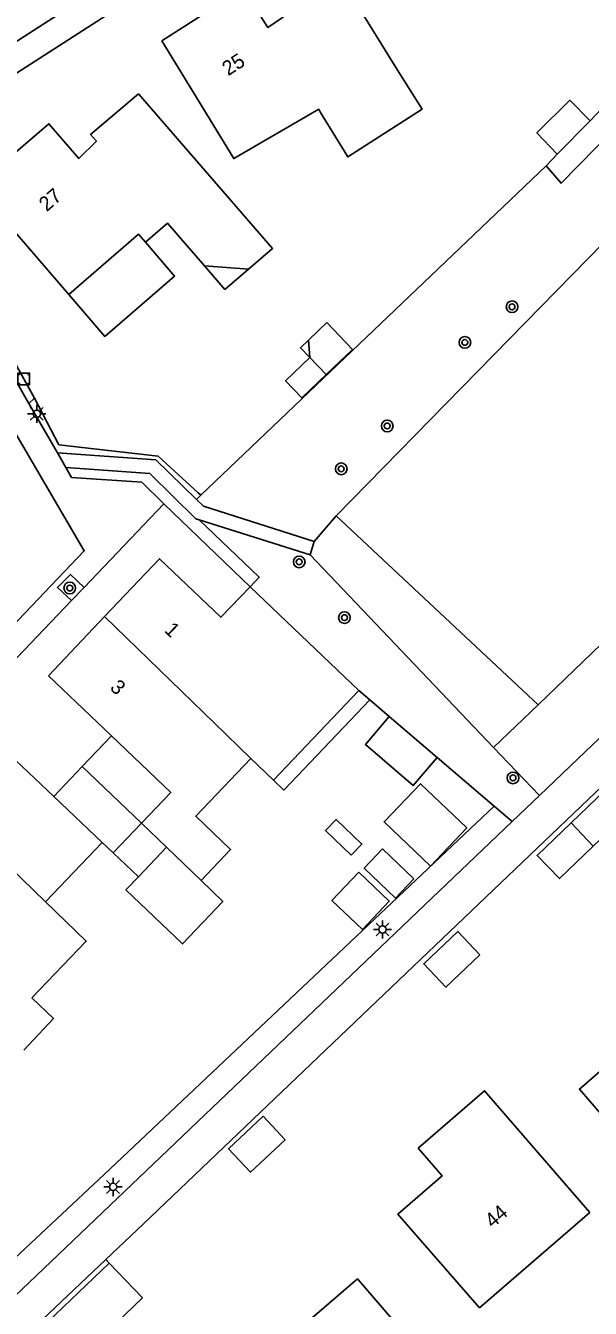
# Model space of a CAD drawing. Extents: x 136000 to 141014, y 402000 to 403500.
# Drawn here: x 137574.1 to 137612.8, y 402325.2 to 402412.9 of the extents above; entities that cross this region are included whole.
import ezdxf

# ---------------------------------------------------------------- set-up
doc = ezdxf.new("R2010")
doc.units = 0
for name, color, linetype in [('gg-afsc-erfafscheiding', 7, 'Continuous'), ('gg-afsc-haag', 7, 'Continuous'), ('gg-anno-huisnummerreeks BGT', 7, 'Continuous'), ('gg-bbg-bijgebouw', 7, 'Continuous'), ('gg-bbg-gedigitaliseerde bebouwing', 7, 'Continuous'), ('gg-bbg-gedigitaliseerde bijgebouw', 7, 'Continuous'), ('gg-bbg-hoofdgebouw', 7, 'Continuous'), ('gg-bbg-luifel en loopbrug', 7, 'Continuous'), ('gg-bbg-tussenscheiding', 7, 'Continuous'), ('gg-knt-verharding', 7, 'Continuous'), ('gg-knt-verharding nz', 7, 'Continuous'), ('gt-grn-groengrens', 7, 'Continuous'), ('gt-grn-vlakafsluiter', 7, 'Continuous'), ('gt-symb-bak', 7, 'Continuous'), ('gt-symb-boom', 7, 'Continuous'), ('gt-symb-lichtmast', 7, 'Continuous')]:
    doc.layers.add(name, color=color, linetype=linetype)

# ---------------------------------------------------------------- blocks, each defined once
blk = doc.blocks.new('gt0-BOOM')
at = {"layer": 'gt-symb-boom'}
for radius in [0.4, 0.2]:
    blk.add_circle((0, 0), radius, dxfattribs=at)
blk = doc.blocks.new('gt0-BAK')
at = {"layer": 'gt-symb-bak'}
for points in [[(-0.3, 0.4), (-0.3, 0.3), (-0.4, 0.3)], [(0.4, 0.3), (0.3, 0.3), (0.3, 0.4)], [(-0.4, -0.3), (-0.3, -0.3), (-0.3, -0.4)], [(0.3, -0.4), (0.3, -0.3), (0.4, -0.3)]]:
    blk.add_lwpolyline(points, dxfattribs=at)
blk.add_lwpolyline([(0.4, -0.4), (-0.4, -0.4), (-0.4, 0.4), (0.4, 0.4)], close=True, dxfattribs=at)
blk = doc.blocks.new('gt0-LMAST')
at = {"layer": 'gt-symb-lichtmast'}
for p, q in [((-0.182, 0.173), (-0.447, 0.438)), ((-0.005, 0.246), (-0.005, 0.621)), ((0.172, 0.173), (0.437, 0.438)), ((-0.255, -0.004), (-0.63, -0.004)), ((-0.182, -0.181), (-0.447, -0.446)), ((-0.005, -0.254), (-0.005, -0.629)), ((0.437, -0.446), (0.172, -0.181)), ((0.245, -0.004), (0.62, -0.004))]:
    blk.add_line(p, q, dxfattribs=at)
blk.add_circle((-0.005, -0.004), 0.25, dxfattribs=at)

msp = doc.modelspace()

# ---------------------------------------------------------------- linework, layer by layer
at = {"layer": 'gg-afsc-erfafscheiding'}
for p, q in [((137612.743, 402406.376), (137614.277, 402407.986)), ((137609.732, 402403.306), (137610.487, 402404.097)), ((137583.58, 402380.19), (137587.723, 402376.195)), ((137587.723, 402376.195), (137589.47, 402374.51)), ((137597.658, 402366.78), (137599, 402365.632)), ((137602.272, 402362.833), (137606.174, 402359.495))]:
    msp.add_line(p, q, dxfattribs=at)
msp.add_lwpolyline([(137606.174, 402359.495), (137579.489, 402334.301), (137535.473, 402293.103)], dxfattribs=at)
at = {"layer": 'gg-afsc-haag'}
for p, q in [((137587.082, 402381.703), (137609.732, 402403.306)), ((137586.102, 402380.768), (137587.082, 402381.703)), ((137586.102, 402380.768), (137585.917, 402380.937))]:
    msp.add_line(p, q, dxfattribs=at)
msp.add_lwpolyline([(137585.917, 402380.937), (137583.179, 402383.439), (137576.394, 402384.217), (137574.711, 402387.417)], dxfattribs=at)
at = {"layer": 'gg-bbg-bijgebouw'}
for p, q in [((137612.743, 402406.376), (137610.487, 402404.097)), ((137582.043, 402358.346), (137580.107, 402356.316))]:
    msp.add_line(p, q, dxfattribs=at)
for points in [[(137605.2, 402349.34), (137603.68, 402350.93), (137601.36, 402348.72), (137602.87, 402347.13), (137605.2, 402349.34)], [(137591.87, 402336.68), (137590.37, 402338.29), (137588, 402336.07), (137589.51, 402334.47), (137591.87, 402336.68)]]:
    msp.add_lwpolyline(points, dxfattribs=at)
at = {"layer": 'gg-bbg-gedigitaliseerde bebouwing'}
for p, q in [((137595.41, 402416.57), (137599.481, 402409.952)), ((137596.92, 402367.412), (137591.071, 402361.273)), ((137591.071, 402361.273), (137589.516, 402362.754)), ((137575.468, 402352.957), (137579.348, 402357.012)), ((137586.115, 402354.415), (137583.751, 402356.697))]:
    msp.add_line(p, q, dxfattribs=at)
for points in [[(137594.297, 402406.943), (137594.167, 402407.166), (137588.36, 402403.796), (137583.43, 402411.85)], [(137599.481, 402409.952), (137601.258, 402407.178), (137596.154, 402403.909), (137594.297, 402406.943)], [(137589.516, 402362.754), (137585.76, 402358.808), (137588.14, 402356.542), (137586.115, 402354.415)], [(137574.538, 402346.389), (137578.267, 402350.265), (137575.468, 402352.957)], [(137573.981, 402342.821), (137576.027, 402344.975), (137574.538, 402346.389)], [(137616.552, 402344.087), (137612.006, 402340.151), (137616.88, 402334.52)], [(137612.71, 402331.71), (137605.514, 402340.03), (137600.976, 402336.105), (137602.611, 402334.214), (137599.586, 402331.597), (137605.16, 402325.18)], [(137601.76, 402321.44), (137596.833, 402327.169), (137592.266, 402323.245)]]:
    msp.add_lwpolyline(points, dxfattribs=at)
at = {"layer": 'gg-bbg-gedigitaliseerde bijgebouw'}
for p, q in [((137594.731, 402392.576), (137593.479, 402391.382)), ((137596.477, 402390.745), (137594.731, 402392.576)), ((137593.564, 402390.178), (137593.479, 402391.382)), ((137594.668, 402389.02), (137593.564, 402390.178)), ((137596.477, 402390.745), (137594.668, 402389.02)), ((137599, 402365.632), (137602.272, 402362.833)), ((137581.832, 402354.677), (137583.751, 402356.697)), ((137580.107, 402356.316), (137581.832, 402354.677)), ((137579.827, 402328.249), (137575.63, 402324.24))]:
    msp.add_line(p, q, dxfattribs=at)
for points in [[(137612.743, 402406.376), (137611.346, 402407.785), (137609.095, 402405.553), (137610.487, 402404.097)], [(137602.272, 402362.833), (137600.639, 402360.923), (137597.366, 402363.721), (137599, 402365.632)], [(137601.811, 402355.394), (137604.303, 402358.009), (137601.128, 402361.034), (137598.637, 402358.419), (137601.811, 402355.394)], [(137611.434, 402358.35), (137613.75, 402360.564), (137615.274, 402358.97), (137612.957, 402356.756)], [(137611.434, 402358.35), (137609.117, 402356.136), (137610.641, 402354.542), (137612.957, 402356.756)], [(137577.923, 402321.839), (137582.106, 402325.862), (137579.827, 402328.249)]]:
    msp.add_lwpolyline(points, dxfattribs=at)
at = {"layer": 'gg-bbg-hoofdgebouw'}
for p, q in [((137589.365, 402396.23), (137586.352, 402396.467)), ((137589.47, 402374.51), (137596.92, 402367.412)), ((137575.674, 402368.41), (137579.511, 402372.463)), ((137575.674, 402368.41), (137579.988, 402364.303)), ((137576.037, 402360.153), (137571.712, 402364.256)), ((137579.348, 402357.012), (137576.037, 402360.153)), ((137605.16, 402325.18), (137612.71, 402331.71))]:
    msp.add_line(p, q, dxfattribs=at)
for points in [[(137583.43, 402411.85), (137588.99, 402415.42), (137590.69, 402412.75), (137592.13, 402413.75), (137591.79, 402414.27), (137595.41, 402416.57)], [(137577.06, 402394.49), (137570.69, 402401.88), (137575.71, 402406.18), (137577.75, 402403.79), (137578.96, 402404.98), (137578.56, 402405.44), (137581.83, 402408.22)], [(137581.83, 402408.22), (137591.014, 402397.645), (137589.365, 402396.23)], [(137586.352, 402396.467), (137583.82, 402399.373), (137582.308, 402398.077)], [(137582.308, 402398.077), (137581.843, 402398.616), (137577.06, 402394.49)], [(137579.511, 402372.463), (137583.27, 402376.42), (137587.47, 402372.42), (137589.47, 402374.51)], [(137579.988, 402364.303), (137584.042, 402360.443), (137582.043, 402358.346)]]:
    msp.add_lwpolyline(points, dxfattribs=at)
at = {"layer": 'gg-bbg-luifel en loopbrug'}
for p, q in [((137596.92, 402367.412), (137597.658, 402366.78)), ((137579.988, 402364.303), (137577.99, 402362.205)), ((137577.99, 402362.205), (137576.037, 402360.153)), ((137582.043, 402358.346), (137577.99, 402362.205)), ((137580.107, 402356.316), (137579.348, 402357.012))]:
    msp.add_line(p, q, dxfattribs=at)
for points in [[(137582.308, 402398.077), (137584.309, 402395.758), (137579.526, 402391.632), (137577.06, 402394.49)], [(137589.365, 402396.23), (137587.755, 402394.841), (137586.352, 402396.467)], [(137593.479, 402391.382), (137592.922, 402390.851), (137593.564, 402390.178)], [(137594.668, 402389.02), (137593.006, 402387.435), (137591.902, 402388.592), (137593.564, 402390.178)], [(137591.071, 402361.273), (137591.773, 402360.604), (137597.658, 402366.78)], [(137596.397, 402356.146), (137594.632, 402357.827), (137595.359, 402358.589), (137597.123, 402356.908), (137596.397, 402356.146)], [(137600.685, 402354.538), (137599.427, 402353.217), (137597.284, 402355.259), (137598.542, 402356.58), (137600.685, 402354.538)], [(137596.907, 402354.979), (137595.07, 402353.05), (137597.157, 402351.063), (137598.993, 402352.992), (137596.907, 402354.979)], [(137581.832, 402354.677), (137580.973, 402353.773), (137584.857, 402350.082), (137587.606, 402352.976), (137586.115, 402354.415)]]:
    msp.add_lwpolyline(points, dxfattribs=at)
at = {"layer": 'gg-bbg-tussenscheiding'}
for p, q in [((137567.895, 402360.24), (137575.468, 402352.957)), ((137582.043, 402358.346), (137583.751, 402356.697)), ((137611.434, 402358.35), (137612.957, 402356.756))]:
    msp.add_line(p, q, dxfattribs=at)
msp.add_lwpolyline([(137579.511, 402372.463), (137587.042, 402365.173), (137589.516, 402362.754)], dxfattribs=at)
at = {"layer": 'gg-knt-verharding'}
for p, q in [((137615.822, 402436.874), (137567.22, 402405.62)), ((137574.345, 402387.053), (137572.372, 402390.48)), ((137574.711, 402387.417), (137574.345, 402387.053)), ((137575.801, 402384.524), (137574.345, 402387.053)), ((137576.299, 402383.659), (137575.801, 402384.524)), ((137576.357, 402383.559), (137576.299, 402383.659)), ((137576.877, 402382.656), (137576.357, 402383.559)), ((137583.58, 402380.19), (137578.113, 402374.467)), ((137593.575, 402376.698), (137585.987, 402379.095)), ((137593.864, 402377.613), (137593.575, 402376.698)), ((137578.113, 402374.467), (137577.244, 402373.557)), ((137577.244, 402373.557), (137566.454, 402362.262)), ((137612.391, 402363.209), (137620.358, 402370.806)), ((137609.272, 402360.235), (137612.391, 402363.209)), ((137607.398, 402358.448), (137609.272, 402360.235))]:
    msp.add_line(p, q, dxfattribs=at)
for points in [[(137635.971, 402427.818), (137610.755, 402402.103), (137609.732, 402403.306)], [(137576.299, 402383.659), (137583.025, 402383.181), (137585.808, 402380.467)], [(137576.877, 402382.656), (137582.606, 402382.248), (137585.769, 402379.164), (137585.987, 402379.095)], [(137583.58, 402380.19), (137582.07, 402381.66), (137577.26, 402381.99), (137576.877, 402382.656)], [(137585.808, 402380.467), (137586.276, 402380.011), (137593.864, 402377.613)], [(137577.244, 402373.557), (137576.291, 402374.456), (137577.183, 402375.349), (137578.113, 402374.467)], [(137622.082, 402368.977), (137582.188, 402330.934), (137579.601, 402328.486)], [(137534.99, 402290.67), (137536.69, 402291.95), (137567.34, 402320.25), (137607.398, 402358.448)], [(137536.59, 402288.82), (137538.25, 402289.99), (137565.219, 402314.877), (137579.601, 402328.486)]]:
    msp.add_lwpolyline(points, dxfattribs=at)
at = {"layer": 'gg-knt-verharding nz'}
for points in [[(137566.24, 402407.15), (137615.35, 402438.77), (137616.513, 402439.142)], [(137556.47, 402354.25), (137578.13, 402376.96), (137566.85, 402396.21)]]:
    msp.add_lwpolyline(points, dxfattribs=at)
at = {"layer": 'gt-grn-groengrens'}
for p, q in [((137595.365, 402379.363), (137615.604, 402400.041)), ((137585.808, 402380.467), (137586.102, 402380.768)), ((137593.864, 402377.613), (137595.365, 402379.363)), ((137609.192, 402366.43), (137595.365, 402379.363)), ((137593.575, 402376.698), (137606.14, 402363.52)), ((137609.192, 402366.43), (137606.14, 402363.52)), ((137609.272, 402360.235), (137606.14, 402363.52)), ((137606.174, 402359.495), (137607.398, 402358.448)), ((137579.601, 402328.486), (137579.827, 402328.249))]:
    msp.add_line(p, q, dxfattribs=at)
for points in [[(137585.987, 402379.095), (137590.095, 402375.163), (137589.47, 402374.51)], [(137620.358, 402370.806), (137617.206, 402374.15), (137609.192, 402366.43)]]:
    msp.add_lwpolyline(points, dxfattribs=at)
at = {"layer": 'gt-grn-vlakafsluiter'}
msp.add_line((137572.796, 402390.863), (137574.711, 402387.417), dxfattribs=at)

# ---------------------------------------------------------------- block references
at = {"layer": 'gt-symb-bak'}
msp.add_blockref('gt0-BAK', (137573.988, 402388.719), dxfattribs=at)
at = {"layer": 'gt-symb-boom'}
for p, rotation in [((137607.399, 402393.659), -165.57446822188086), ((137604.172, 402391.221), -165.57446821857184), ((137598.859, 402385.506), -165.57446821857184), ((137595.708, 402382.573), -165.57446821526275), ((137595.928, 402372.397), 12.771242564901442), ((137607.463, 402361.432), 12.771242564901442)]:
    msp.add_blockref('gt0-BOOM', p, dxfattribs=dict(at, rotation=rotation))
for p in [(137592.833, 402376.206), (137577.134, 402374.419)]:
    msp.add_blockref('gt0-BOOM', p, dxfattribs=at)
at = {"layer": 'gt-symb-lichtmast'}
for p in [(137574.881, 402386.339), (137598.541, 402351.067), (137580.103, 402333.458)]:
    msp.add_blockref('gt0-LMAST', p, dxfattribs=at)

# ---------------------------------------------------------------- texts
at = {"layer": 'gg-anno-huisnummerreeks BGT'}
for s, rotation, p in [('25', 32.7, (137587.971, 402409.418)), ('27', 40.6, (137575.555, 402400.12)), ('1', 316.5, (137583.551, 402371.472)), ('3', 316.6, (137579.824, 402367.541)), ('44', 40.9, (137606.072, 402330.595))]:
    msp.add_text(s, height=1, rotation=rotation, dxfattribs=at).set_placement(p)

doc.saveas('drawing.dxf')
